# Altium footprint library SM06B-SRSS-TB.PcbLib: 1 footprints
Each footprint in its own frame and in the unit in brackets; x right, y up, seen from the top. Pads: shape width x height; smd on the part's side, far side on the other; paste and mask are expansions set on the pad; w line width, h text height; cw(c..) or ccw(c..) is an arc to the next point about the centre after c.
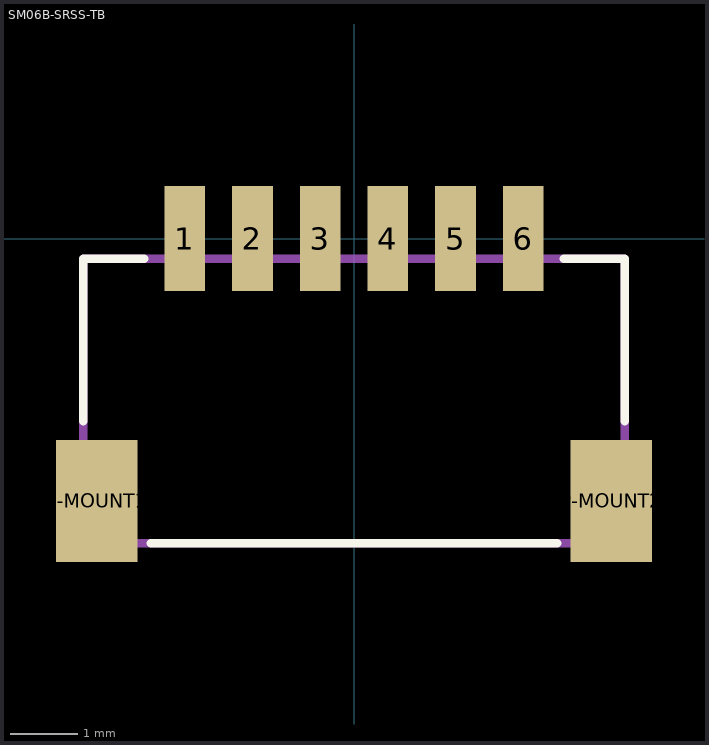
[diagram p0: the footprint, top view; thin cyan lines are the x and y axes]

## SM06B-SRSS-TB [mm]
pads (8):
  rect 0.6x1.55 smd: 1(-2.5,0) 2(-1.5,0) 3(-0.5,0) 4(0.5,0) 5(1.5,0) 6(2.5,0)
  rect 1.2x1.8 smd: P-MOUNT1(-3.8,-3.875) P-MOUNT2(3.8,-3.875)
Top Overlay:
  lines w0.127: -4,-2.7 -4,-0.3 -3.1,-0.3 ; -3,-4.5 3,-4.5 ; 3.1,-0.3 4,-0.3 4,-2.7
Assembly Top:
  lines w0.127: -4,-4.5 -4,-0.3 4,-0.3 4,-4.5 -4,-4.5
3D body "step_temp.STEP": height 2.95, standoff 0, extent -4,-4.572 4,0.378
